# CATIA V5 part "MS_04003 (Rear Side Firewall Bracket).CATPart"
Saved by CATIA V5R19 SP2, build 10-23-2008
Part number: MS_04003 (Rear Side Firewall Bracket)
Bounding box of the stored display mesh (mm): x -1308.099 to 0, y -314.304 to 0, z 0 to 167.952
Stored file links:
  D:\EPSA\GIT\ELIZ-2022\01 - Maquette CATIA\MS_Miscellanous_Finish_Assembly\MS_A0400 (Firewall)\MS_04003 (Rear Side Firewall Bracket).CATPart
  D:\EPSA\GIT\ELIZ-2022\01 - Maquette CATIA\MS_Miscellanous_Finish_Assembly\MS_A0400 (Firewall)\MS_A0400 (FireWall).CATProduct
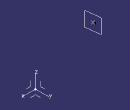
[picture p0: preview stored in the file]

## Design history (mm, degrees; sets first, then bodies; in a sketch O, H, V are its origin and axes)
AxisSystem1: origin (0, 0, 0), X (1, 0, 0), Y (0, 1, 0), Z (0, 0, 1)
Set1
  Point1: type OnCurve, Support Line1, Length 155.604
  Plane1: type Normal, Curve Line1, RefPoint Point1
  Sketch1 on Plane1, origin (-1296.0405, -161.2004, 0.4003), H (-0.1234, 0.9924, 0), V (0.0003, 0, 1)
    circle A1 centre (-154.2898, 167.552) radius 14
    point P1 (-154.2898, 167.552)
    reference projected point E1 (-154.2898, 167.552) from Point1
    radius A1 = 14
    coincidence: P1 E1
Set2
  Line1: linked copy from another document
  DatumSurface1: linked copy from another document
  DatumSurface2: linked copy from another document
Body1 (main body)
  Pad1: profile Sketch1, direction (0.9924, 0.1234, -0.0003), length 50, opposite side length 110
  Point2: type OnSurface, Support face of Pad1 from Sketch1.A1, Length 23.421, Direction (0.131, 0.5823, -0.8024)
  Plane2: type Tangent, Support DatumSurface1, RefPoint Point2
  Point3: type OnPlane, Support Plane2, H -1351.74, V 167.509, Direction (0.9924, 0.1234, 0)
  Line2: type PtPt, FirstPoint Point2, SecondPoint Point3, Start 55, End 24
Body2
  Sketch2 on face of DatumSurface2, origin (13.2848, -107.2449, -18.6878), H (0.9924, 0.1229, 0), V (0.0209, -0.1691, 0.9854)
    reference projected line E1 through (0.074, 191.3929) direction (1, -0.0004) from axis of face of Pad1 from Sketch1.A1
    construction line L1 (-1327.9759, 191.9066) -> (-1327.9859, 165.9066)
    point P3 (-1327.9759, 191.9066)
    reference projected point E2 (-1327.9768, 189.4748) from Point2
    arc A1 centre (-1327.9859, 165.9066) radius 7 from (-1334.9859, 165.9093) to (-1327.9886, 158.9066) ccw
    point P5 (-1327.9886, 158.9066)
    point P6 (-1334.9859, 165.9093)
    line L2 (-1334.9859, 165.9093) -> (-1334.9759, 191.9093)
    point P7 (-1334.9759, 191.9093)
    line L3 (-1334.9759, 191.9093) -> (-1327.9759, 191.9066)
    circle A2 centre (-1327.9859, 165.9066) radius 1.7
    point P8 (-1327.9759, 191.9066)
    point P9 (-1320.9759, 191.9039)
    line L4 (-1320.9759, 191.9039) -> (-1327.9759, 191.9066)
    point P10 (-1320.9859, 165.9039)
    line L5 (-1320.9859, 165.9039) -> (-1320.9759, 191.9039)
    point P11 (-1327.9886, 158.9066)
    arc A3 centre (-1327.9859, 165.9066) radius 7 from (-1320.9859, 165.9039) to (-1327.9886, 158.9066) cw
    radius A1 = 7
    length L2 = 26
    radius A2 = 1.7
    coincidence: P3 E1, L1 E2, P5 L1, P7 E1, P3 P8, P5 P11
    perpendicularity: L1 E1
    tangency: L2 A1
    parallelism: L3 E1, L1 L2
    symmetry: P3 P8 L1, P7 P9 L1, L3 L4 L1, P6 P10 L1, L2 L5 L1, P5 P11 L1, A1 A3 L1
  Pad2: profile Sketch2, direction (0.1211, -0.9779, -0.1704), length 1.5
  Sketch3 on end face of Pad2, origin (13.4665, -108.7117, -18.9434), H (0.9924, 0.1229, 0), V (0.0209, -0.1691, 0.9854)
    intersected line E1 (-1415.9064, 186.5822) -> (-1255.9065, 186.3541) from face of Pad1 from Sketch1.A1
    intersected line E2 (-1415.9023, 197.2991) -> (-1255.9022, 197.4034) from face of Pad1 from Sketch1.A1
    line L1 (-1415.9023, 197.2991) -> (-1415.9064, 186.5822)
    line L2 (-1255.9022, 197.4034) -> (-1255.9065, 186.3541)
  Pocket1: profile Sketch3, direction (-0.1211, 0.9779, 0.1704), up to start face of Pad2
